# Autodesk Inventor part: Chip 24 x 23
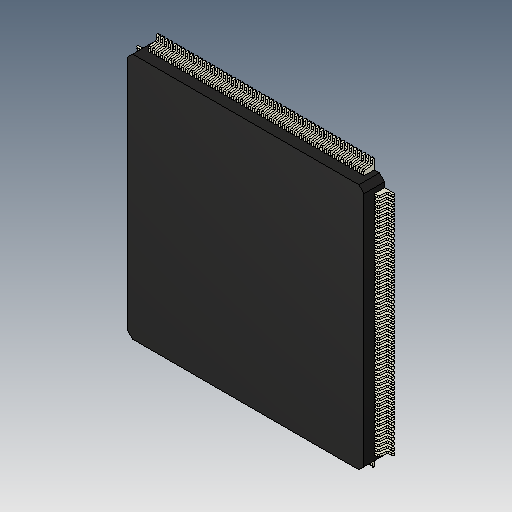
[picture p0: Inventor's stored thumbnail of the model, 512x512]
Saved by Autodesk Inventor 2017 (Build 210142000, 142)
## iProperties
Created: 2005-12
Part Number: Chip 24 x 23
Material: Generic
Document SubType Name: Modeling
Designer: DanielSeverino
Density: 1 g/cm^3
Appearance: Default
Author: DanielSeverino
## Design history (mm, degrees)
feature "Solid1"
body "Solid2"
